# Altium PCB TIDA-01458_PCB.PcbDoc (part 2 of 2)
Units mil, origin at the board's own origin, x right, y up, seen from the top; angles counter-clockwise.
Board outline 4724.41 x 3937.01 mil, 4 copper layers (Top Layer, GND, PWR, Bottom Layer), stack 62.2 mil thick; 188 components, 87 nets, 511 pads, 463 vias.
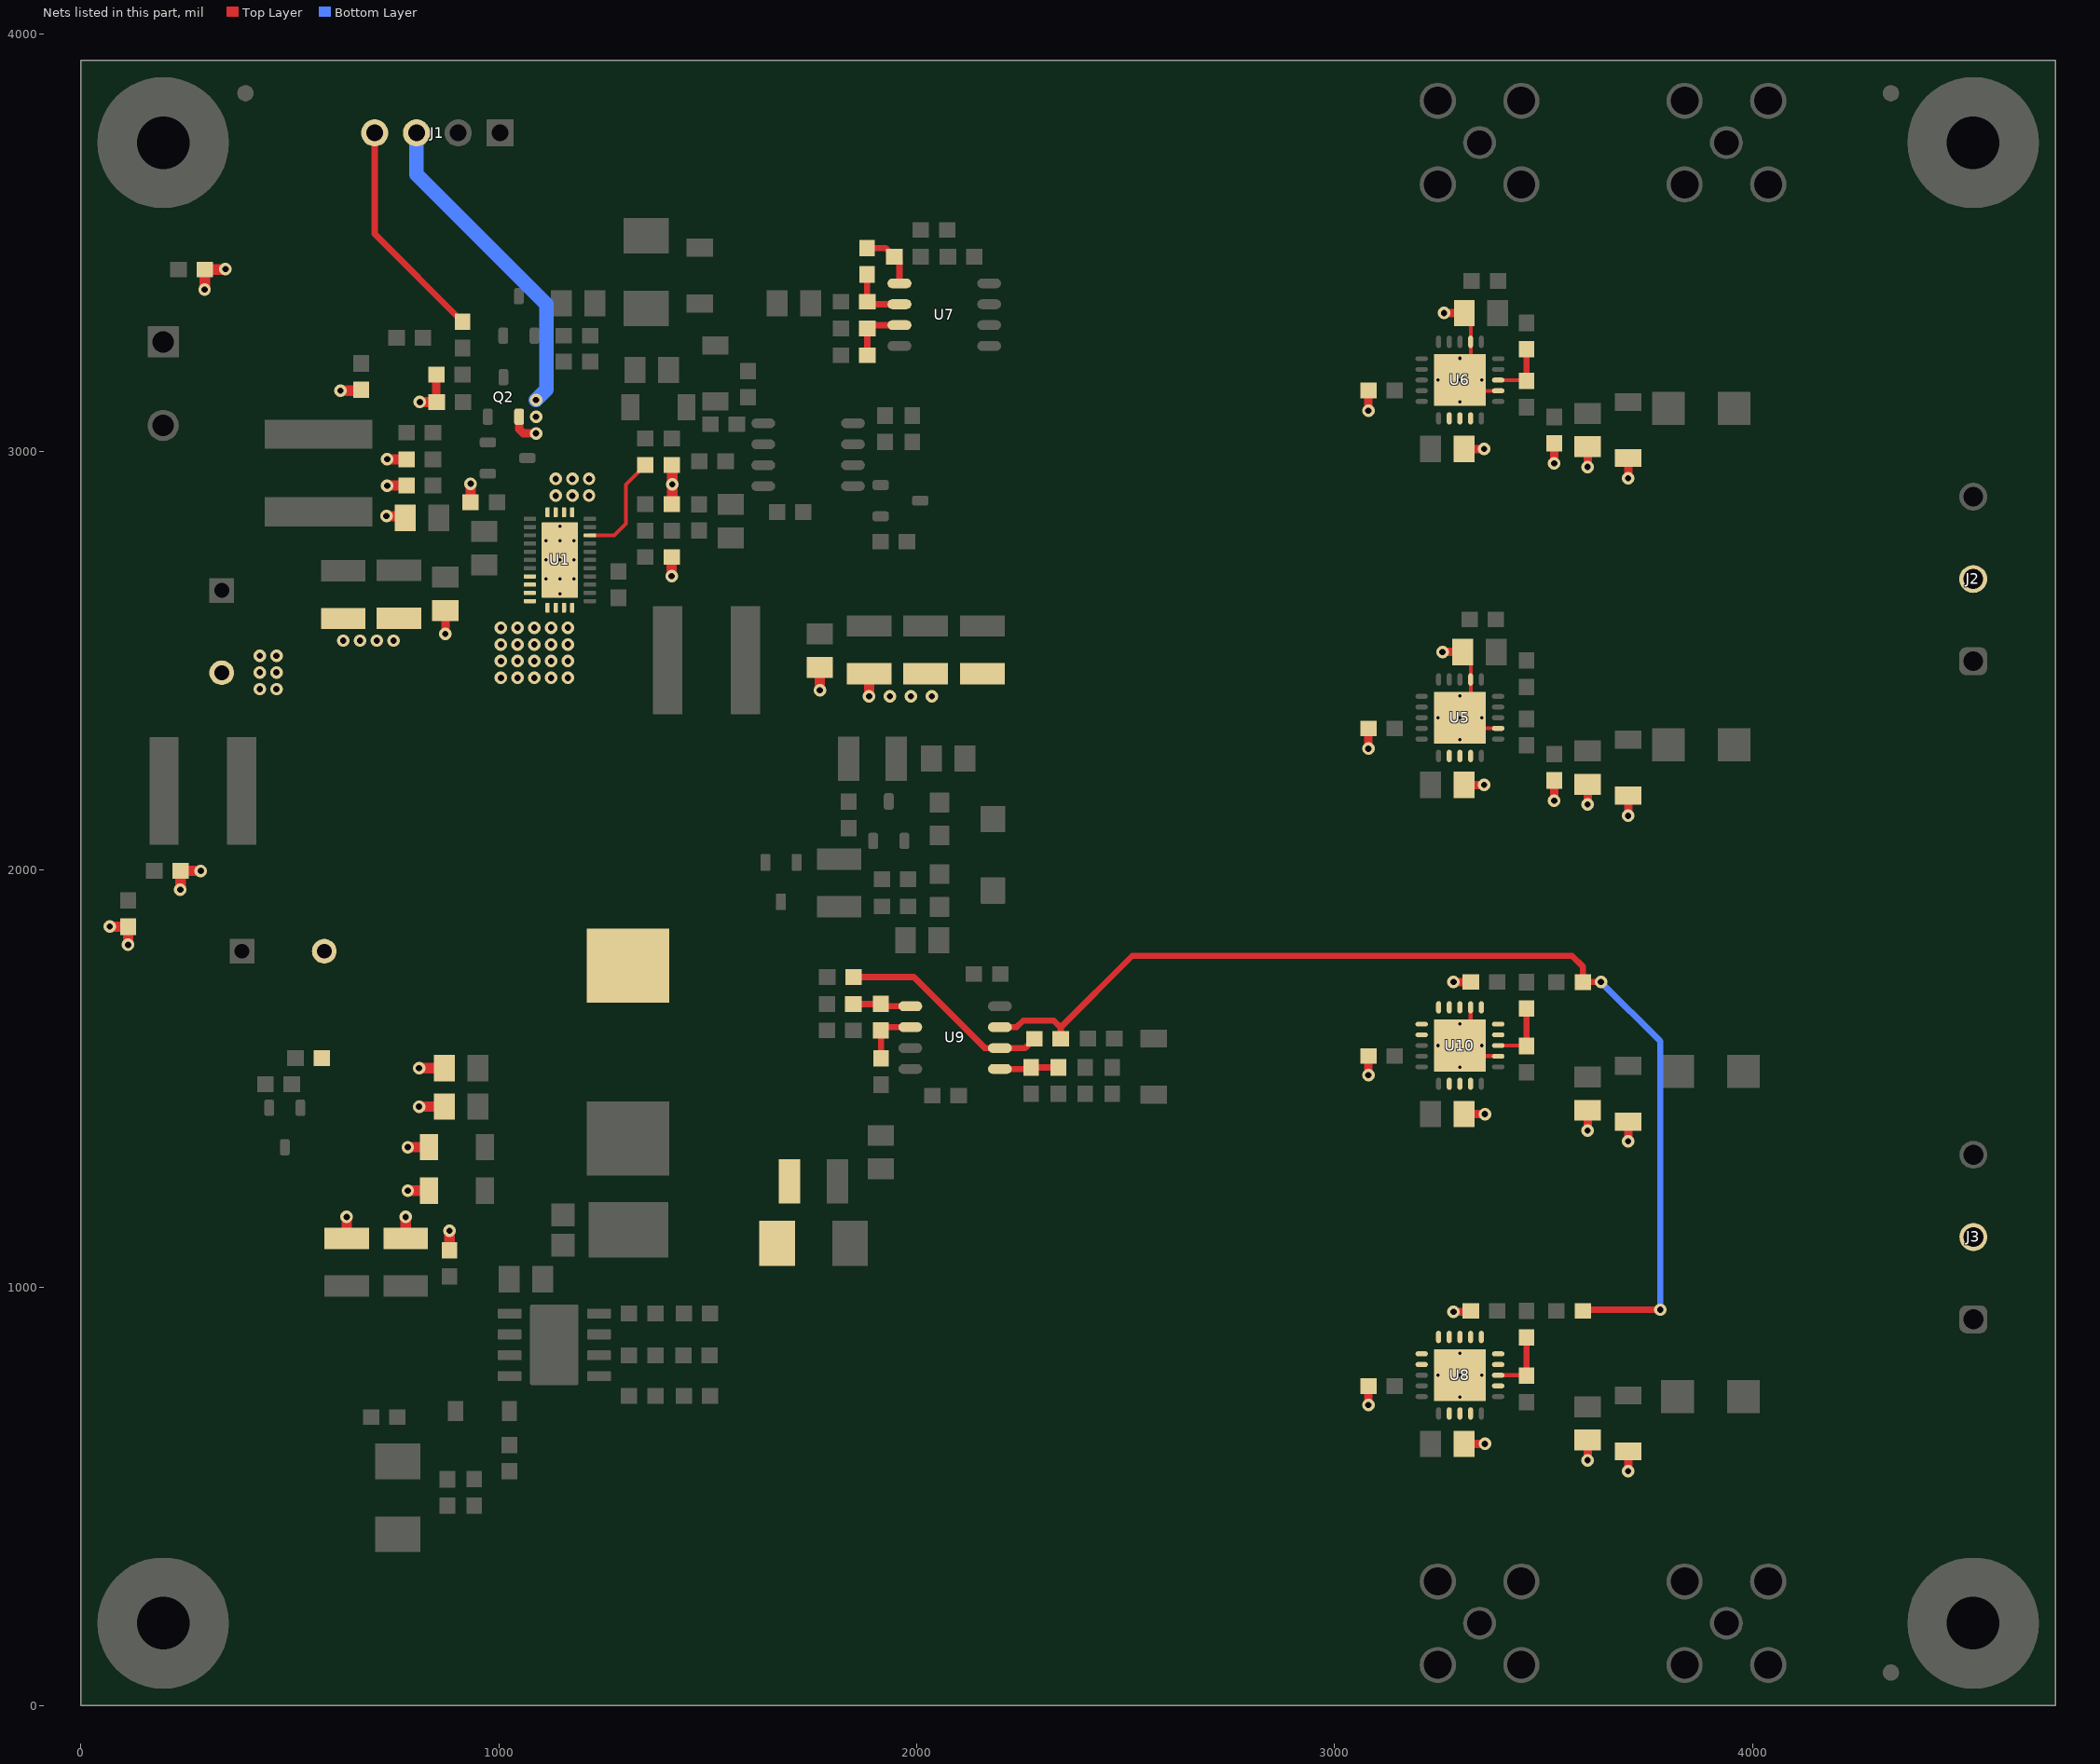
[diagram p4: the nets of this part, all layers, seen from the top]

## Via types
v1: diameter 30, hole 15, Top Layer to Bottom Layer, tented both sides, 424 vias
v2: diameter 19.68, hole 7.87, Top Layer to Bottom Layer, 39 vias

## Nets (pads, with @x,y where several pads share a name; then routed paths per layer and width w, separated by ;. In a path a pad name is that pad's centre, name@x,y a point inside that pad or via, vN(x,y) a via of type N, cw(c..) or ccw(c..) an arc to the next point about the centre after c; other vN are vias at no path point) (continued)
NetR35_2: R35.2 R37.1 U6.3 | length 144.3
  Top Layer w9: U6.3@3391.03,3171.79 3457.21,3171.79 R35.2@3459,3170 R35.2@3459,3189
  Top Layer w15: R35.2@3459,3189 R37.1@3459,3245.54
NetR36_1: R36.1 R39.2 U7.1 | length 142.9
  Top Layer w15: R36.1@1881,3487.75 1925.9,3487.75 R39.2@1946.35,3467.3 1958.57,3455.08 U7.1@1958.57,3403.3
NetR36_2: R36.2 R38.1 U7.2 | length 145.2
  Top Layer w15: R36.2@1881,3424.76 1881,3359.75 R38.1@1881.5,3359.25 1887.45,3353.3 U7.2@1958.57,3353.3
NetR41_1: R41.1 R42.2 U7.3 | length 147
  Top Layer w15: R42.2@1881.5,3229.22 R41.1@1881.5,3295.25 1889.54,3303.3 U7.3@1958.57,3303.3 ; R42.2@1881.54,3231.19 R42.2@1881.97,3230.76
NetR43_1: R43.1 R46.1 U8.3 | length 158
  Top Layer w10: U8.3@3391.03,790.25 R43.1@3457.68,790.25
  Top Layer w15: R43.1@3457.68,790.25 3459,791.57 R46.1@3459,881.01
NetR44_1: R44.1 R45.2 U9.2 | length 141.2
  Top Layer w15: R44.1@1914.72,1548.75 1914.72,1614.76 R45.2@1913.72,1615.76 1921.21,1623.25 U9.2@1984.43,1623.25
NetR45_1: R45.1 R48.1 U9.1 | length 138.7
  Top Layer w15: R48.1@1848.21,1678.25 1848.71,1678.75 R45.1@1913.72,1678.75 1919.21,1673.25 U9.1@1984.43,1673.25
NetR47_2: R47.2 R51.1 R57.2 U9.7 | length 2627.2
  Top Layer w15: U9.7@2199,1623.25 2238.84,1623.25 2254.59,1639 2328,1639 2344.21,1622.79 ; R51.1@2344.21,1595.25 2344.21,1622.79 ; R47.2@3593.5,944 3596.5,947 v1(3779,947) ; v1(3636.82,1731.18) R57.2@3593.5,1731.18 3593.5,1768.5 3568,1794 2515.43,1794 2344.21,1622.79
  Bottom Layer w15: v1(3636.82,1731.18) 3779,1589 v1(3779,947)
NetR50_1: R50.1 R51.2 U9.6 | length 512.1
  Top Layer w15: R50.1@1848.67,1743.23 1992.77,1743.23 2162.75,1573.25 U9.6@2199,1573.25 2259.22,1573.25 R51.2@2281.22,1595.25
NetR52_1: R52.1 R55.1 U10.3 | length 155.6
  Top Layer w9: U10.3@3391.03,1579.25 R52.1@3452.5,1579.25
  Top Layer w15: R52.1@3452.5,1579.25 3454,1577.75 R52.1@3454,1578 ; R55.1@3454,1667.76 3458.93,1662.82 R52.1@3458.93,1578
NetR53_2: R53.2 R54.2 U9.5 | length 141.2
  Top Layer w15: U9.5@2199,1523.25 2270.22,1523.25 R53.2@2273.72,1526.75 R54.2@2338.72,1526.75
NetR58_1: R58.1 U1.9 | length 257
  Top Layer w9: U1.9@1217.85,2800.31 1276.06,2800.31 1304,2828.25 1304,2921.75 R58.1@1350.5,2968.25
PGND_A: C2.2 C3.1 C4.1 C5.1 C6.1 C7.1 C8.2 C9.2 C10.2 C11.1 C12.2 C15.2 C65.2 J1.3 Q2.2 R3.1 R6.1 R10.1 R58.2 R59.1 U1.12 U1.13 U1.14 U1.15 U1.23 U1.24 U1.25 U1.26 U1.27 U1.28 U1.29 U1.30 U1.31 | length 1479.6
  Top Layer w20: C65.2@850.5,3185 850.5,3120.25 R10.1@851.5,3119.25 ; v1(872,2564.25) C6.1@872,2620.25 ; Q2.2@1048.4,3084.01 1048.4,3054.85 1059,3044.25 v1(1089,3044.25) v1@1094,3044.25
  Top Layer w25: v1(621,3146.25) 668.5,3146.25 R59.1@671,3148.76 ; v1(731,2846.25) 757,2846.25 R3.1@761,2842.25 ; v1(733,2919.25) C12.2@768.5,2919.25 ; v1(733,2982.25) C15.2@779.5,2982.25 ; v1(811,3119.25) R10.1@851.5,3119.25 ; R6.1@932.5,2879.25 v1(932.5,2923.76) ; v1(1413.5,2702.76) C3.1@1413.5,2748.25 ; C11.1@1413.5,2875.05 1415,2876.56 v1(1415,2922.25) 1415,2966.88 R58.2@1413.5,2968.39 ; v1(1768,2429.25) C7.1@1768,2484.25 ; v1(1886,2415.25) C9.2@1886,2469.17
  Bottom Layer w15: J1.3@803,3763.25 J1.3@804,3762.25
  Bottom Layer w35: J1.3@803,3763.25 803,3664.25 1114,3353.25 1114,3149.25 v1(1089,3124.25)
  other v1: 1936,2415.25 1986,2415.25 2036,2415.25 428,2432.25 468,2432.25 1005,2459.25 1045,2459.25 1085,2459.25 1125,2459.25 1165,2459.25 428,2472.25 468,2472.25 1005,2499.25 1045,2499.25 1085,2499.25 1125,2499.25 1165,2499.25 428,2512.25 468,2512.25 1005,2539.25 1045,2539.25 1085,2539.25 1125,2539.25 1165,2539.25 628,2548.25 668,2548.25 708,2548.25 748,2548.25 1005,2579.25 1045,2579.25 1085,2579.25 1125,2579.25 1165,2579.25 1136,2895.25 1176,2895.25 1216,2895.25 1136,2935.25 1176,2935.25 1216,2935.25 1089,3084.25
  other v2: 1146,2660.54 1112.54,2695.58 1146,2695.58 1179.46,2695.58 1112.54,2741.25 1146,2741.25 1179.46,2741.25 1112.54,2786.92 1146,2786.92 1179.46,2786.92 1146,2821.96
PGND_B: C23.2 C24.2 C25.2 C26.2 C29.1 C30.1 C31.1 C33.2 C62.1 D4.1 L2.2 R23.1 R60.1 | length 441.7
  Top Layer w25: v1(238,1952.25) 238.5,1952.75 R60.1@238.5,1997.25 v1(287,1997.25) ; C23.2@636,1118.09 v1(636,1169) ; C24.2@777,1118.09 v1(777,1169) ; v1(782.16,1232) C62.1@833.07,1232 ; v1(782.16,1336) C31.1@833.07,1336 ; v1(809.09,1433) C30.1@860,1433 ; v1(809.09,1525) C29.1@860,1525 ; C25.2@882,1093.5 v1(882,1136)
REGM: C49.1 C50.2 C51.1 C53.1 C56.1 C57.2 C58.1 C59.1 C60.1 C61.1 J3.2 R62.1 U8.2 U8.4 U8.5 U8.6 U8.7 U8.8 U8.9 U8.10 U8.11 U8.12 U8.17 U8.18 U8.19 U8.21 U10.2 U10.4 U10.5 U10.6 U10.7 U10.8 U10.9 U10.10 U10.11 U10.12 U10.17 U10.18 U10.19 U10.21 | length 721.4
  Top Layer w10: v2(3299.5,1579.25) 3325.09,1604.84 U10.7@3325.09,1670.79 ; U10.21@3325.09,1553.66 U10.2@3391.03,1553.66
  Top Layer w20: v1(3080.5,719.25) C60.1@3080.5,764.25 C60.1@3080.5,765 ; v1(3080.5,1508.5) C61.1@3080.5,1554.25 ; v1(3284.25,942) C53.1@3325.5,942 ; v1(3284.25,1731.25) C59.1@3325.5,1731.25 ; C51.1@3309,626 v1(3359.25,626) ; C58.1@3309,1415.25 v1(3359.25,1415.25) ; v1(3605,586.75) C49.1@3605,635 ; v1(3605,1376) C56.1@3605,1424.25 ; v1(3702,560.75) C50.2@3702,608.07 ; v1(3702,1350) C57.2@3702,1397.32
  Top Layer w25: v1(69,1864.25) 69.5,1863.76 R62.1@113,1863.76 v1(113,1820.25)
  other v2: 3299.5,738.09 3247.33,790.25 3299.5,790.25 3351.66,790.25 3299.5,842.42 3299.5,1527.09 3247.33,1579.25 3351.66,1579.25 3299.5,1631.42
REGP: C34.1 C35.2 C36.2 C37.1 C38.1 C39.1 C40.1 C41.2 C42.2 C43.1 C46.1 C47.1 J2.2 R61.1 U5.2 U5.7 U5.17 U5.18 U5.19 U5.21 U6.2 U6.7 U6.17 U6.18 U6.19 U6.21 | length 1232.8
  Top Layer w9: C39.1@3310,2521 3325.09,2505.91 U5.7@3325.09,2455.32 3325.09,2389.38 v2(3299.5,2363.79) 3325.09,2338.2 U5.2@3391.03,2338.2 ; C47.1@3310,3332.25 3325.09,3317.17 U6.7@3325.09,3263.32 3325.09,3197.38 v2(3299.5,3171.79) 3325.09,3146.2 U6.2@3391.03,3146.2
  Top Layer w20: v1(3080.5,2289.75) C38.1@3080.5,2338 ; v1(3080.5,3098.75) C46.1@3080.5,3147 ; v1(3257.75,2521) C39.1@3306,2521 ; v1(3261.75,3332.25) C47.1@3310,3332.25 ; C37.1@3309,2203 v1(3357.25,2203) ; C43.1@3309,3007 v1(3357.25,3007) ; v1(3525,2165.5) C36.2@3525,2213.76 ; v1(3525,2972.25) C42.2@3525,3020.5 ; v1(3605,2156) C34.1@3605,2204.25 ; v1(3605,2964) C40.1@3605,3012.25 ; v1(3702,2129.07) C35.2@3702,2177.32 ; v1(3702,2937.07) C41.2@3702,2985.32
  Top Layer w25: v1(296,3388.25) 296.5,3388.75 R61.1@296.5,3436.25 345,3436.25 v1(346,3437.25)
  other v2: 3299.5,2311.62 3247.33,2363.79 3351.66,2363.79 3299.5,2415.95 3299.5,3119.62 3247.33,3171.79 3351.66,3171.79 3299.5,3223.95
SYNC: J1.4 R30.1 | length 538.7
  Top Layer w15: J1.4@703,3763.25 703,3521.5 R30.1@913,3311.5
pads on no net: FID1.1 FID2.1 FID3.1 H1.1 H2.1 H5.1 H6.1 U1.16 U1.31A U4.9@1132.72,863 U5.4 U5.5 U5.6 U5.8 U5.9 U5.10 U5.11 U5.12 U6.4 U6.5 U6.6 U6.8 U6.9 U6.10 U6.11 U6.12

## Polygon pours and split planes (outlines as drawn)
PGND_B on Top Layer "GND-No Net" (solid, pour order 236): 551,1831 551,1103 585,1069 901,1069 906,1074 906,1613 956,1663 1436,1663 1585,1514 1585,1049 1609,1025 1694,1025 1726,1057 1726,1748 1598,1876 822,1876 596,1876
-VO on Top Layer "GND-No Net" (solid, pour order 230): 920,1514 920,1220 1045,1095 1071,1069 1071,1015 1071,470 1015,414 948,347 784,347 457,347 415,305 398,288 398,104 398,67 462,3 526,3 2886,3 3000,117 3000,1314 2943,1371 2599,1371 2168,1371 2123,1326 2083,1286 2083,1056 2041,1014 1739,1014 1667,1014 1617,964 1602,949 1602,761 1602,716 1563,677 1241,677 1221,697 1194,724 1194,843 1194,860 1210,876 1216,876 1533,876 1536,879 1536,896 1532,900 1210,900 1203,907 1191,919 1191,1607 1157,1641 959,1641 920,1602
PGND_A on Top Layer "Top Layer-No Net" (solid, remove dead copper, pour order 146): 715,2824.25 722,2817.25 732,2807.25 757,2807.25 799,2807.25 803,2811.25 803,2864.25 803,2998.25 798,3003.25 797,3004.25 738,3004.25 732,3004.25 715,2987.25
+3.3V on Top Layer "Bottom Layer-No Net" (solid, remove dead copper, pour order 109): 1195,3363.25 1195,3197.25 1202.2,3190.05 1256,3190.05 1282.98,3217.02 1282.98,3234 1295.99,3247.01 1445.01,3247.01 1513,3315 1513,3385.25 1484,3414.25 1439,3414.25 1217,3414.25 1195,3392.25
NetC2_1 on Top Layer "Bottom Layer-No Net" (solid, remove dead copper, pour order 145): 564,2903.25 691,2903.25 697,2897.25 699,2895.25 699,2820.25 692,2813.25 689,2810.25 663,2810.25 424,2810.25 368,2754.25 368,2716.25 381,2703.25 413,2703.25 497,2787.25 642,2787.25 869,2787.25 888,2768.25 892,2764.25 1052,2764.25 1082,2764.25 1086,2760.25 1087,2759.25 1087,2733.25 1087,2718.25 1084,2715.25 1017,2715.25 1005,2703.25 976,2674.25 842,2674.25 469,2674.25 422,2627.25 308,2627.25 303,2632.25 294,2641.25 294,2767.25 331,2804.25 331,2889.25 345,2903.25
24VIN on Top Layer "Bottom Layer-No Net" (solid, remove dead copper, pour order 144): 1763,2275.25 1763,2173.25 1781,2155.25 1796,2140.25 1834,2140.25 1938,2140.25 1944,2146.25 1945,2147.25 1945,2175.25 1945,2181.25 1941,2185.25 1916,2185.25 1893,2208.25 1878,2223.25 1878,2262.25 1878,2308.25 1866,2320.25 1830,2320.25 1800,2320.25 1763,2283.25
24VIN on Top Layer "Bottom Layer-No Net" (solid, remove dead copper, pour order 140): 117,3111.25 675,3111.25 699,3087.25 699,2988.25 670,2959.25 330,2959.25 310,2939.25 310,2816.25 245,2751.25 245,2062.25 227,2044.25 61,2044.25 26,2079.25 26,2206.25 26,3050.15 52,3076.15 87.1,3111.25
16V on Top Layer "Bottom Layer-No Net" (solid, remove dead copper, pour order 107): 1951,2079.25 1951,1965.25 1958,1958.25 1960,1956.25 1991,1956.25 2105,1956.25 2121,1972.25 2121,2094.25 2105,2110.25 1975,2110.25 1962,2110.25 1951,2099.25
+VO on Top Layer "Bottom Layer-No Net" (solid, remove dead copper, pour order 106): 1520,2369.25 1536,2353.25 1669,2353.25 1675,2359.25 1675,2496.25 1712,2533.25 1958,2533.25 2204,2533.25 2218.72,2547.98 2218.72,2638.53 2192,2665.25 1694,2665.25 1669,2690.25 1626,2733.25 1626,2750.25 1626,2802.25 1592,2836.25 1540,2836.25 1465,2836.25 1457.5,2828.75 1457.5,2727.75 1520,2665.25
NetC1_1 on Top Layer "Bottom Layer-No Net" (solid, remove dead copper, pour order 99): 1209,2726.25 1234,2726.25 1247,2726.25 1254,2719.25 1254,2681.25 1264,2671.25 1352,2671.25 1446,2671.25 1464,2671.25 1493,2642.25 1493,2369.25 1476,2352.25 1327,2352.25 1203,2476.25 1203,2720.25
PGND_A on Top Layer "Bottom Layer-No Net" (solid, remove dead copper, pour order 98): 860,2645.25 466,2645.25 305,2484.25 305,2409.25 334.19,2380.06 751.19,2380.06 919,2212.25 1321,2212.25 1675,2212.25 1815,2352.25 2197,2352.25 2224.81,2380.06 2224.81,2491.06 2203,2512.88 2166,2512.88 1739.38,2512.88 1701,2474.5 1701,2354.25 1675,2328.25 1321,2328.25 1188,2461.25 1188,2544.25 1188,2648.25 1188,2845.25 1257,2914.25 1257,3071 1182.25,3145.75 1085.5,3145.75 1072,3132.25 1072,3034.25 1104,3002.25 1104,2870.25 1104,2831.25 1104,2716.25 1097,2709.25 1092,2704.25 1053,2704.25 1038,2689.25 994,2645.25 905,2645.25
NetC49_2 on Top Layer "GND-No Net" (solid, pour order 148): 3394,748 3508,748 3532,772 3547,787 3735,787 3859,787 3868,778 3870,776 3870,712 3870,679 3615,679 3353,679 3348,679 3341,686 3341,713 3345,717 3355,717 3366,717 3369,720 3374,725 3374,735 3374,744 3378,748
NetC56_2 on Top Layer "GND-No Net" (solid, pour order 150): 3394,1537 3508,1537 3532,1561 3547,1576 3735,1576 3859,1576 3868,1567 3870,1565 3870,1501 3870,1487 3851,1468 3615,1468 3353,1468 3348,1468 3341,1475 3341,1502 3345,1506 3355,1506 3366,1506 3369,1509 3374,1514 3374,1524 3374,1533 3378,1537
NetC34_2 on Top Layer "GND-No Net" (solid, pour order 152): 3394,2321.54 3508,2321.54 3532,2345.54 3547,2360.54 3735,2360.54 3859,2360.54 3868,2351.54 3870,2349.54 3870,2285.54 3870,2271.54 3851,2252.54 3615,2252.54 3353,2252.54 3348,2252.54 3341,2259.54 3341,2286.54 3345,2290.54 3355,2290.54 3366,2290.54 3369,2293.54 3374,2298.54 3374,2308.54 3374,2317.54 3378,2321.54
NetC40_2 on Top Layer "GND-No Net" (solid, pour order 154): 3394,3129.54 3508,3129.54 3532,3153.54 3547,3168.54 3735,3168.54 3870,3168.54 3870,3093.54 3870,3079.54 3851,3060.54 3615,3060.54 3353,3060.54 3348,3060.54 3341,3067.54 3341,3094.54 3345,3098.54 3355,3098.54 3366,3098.54 3369,3101.54 3374,3106.54 3374,3116.54 3374,3125.54 3378,3129.54
REGP on Top Layer "Top Layer-No Net" (solid, remove dead copper, pour order 158): 3100.99,2336.25 3100.99,2184.25 3135.99,2149.25 3256.49,2149.25 3271.5,2164.25 3271.5,2290.25 3237.64,2324.11 3237.64,2340.39 3237.64,2417.52 3241.7,2421.58 3246.37,2426.25 3290.99,2426.25 3309.8,2426.25 3317.41,2433.86 3317.99,2434.45 3317.99,2460.25 3317.99,2475.25 3313.99,2479.25 3308.99,2484.25 3291.99,2484.25 3251.79,2484.25 3231.5,2504.55 3231.5,2542.25 3247.5,2558.25 3306.99,2558.25 3329.99,2558.25 3330.99,2559.25 3331.99,2558.25 3331.99,2436.25 3342.99,2425.25 3361.35,2406.89 3361.35,2340.39 3361.35,2310.06 3357.29,2305.99 3344.2,2305.99 3331.99,2293.79 3331.99,2247.62 3337.18,2242.44 3342.36,2237.25 3374.99,2237.25 3806.75,2237.25 4058,1986 4058,1874 4018,1834 2956,1834 2834,1956 2834,2314 2882.85,2362.85 3092.35,2362.86 3094.85,2362.86 3100.99,2356.71
+VO on Top Layer "Bottom Layer-No Net" (solid, remove dead copper, pour order 162): 3255.5,2979.26 3249.5,2973.25 3144.04,2973.25 3118.07,2999.23 3118.07,3012.57 3118.07,3058.82 3186.5,3127.25 3220.5,3127.25 3226.5,3121.25 3226.5,3109.25 3226.5,3105.25 3231.5,3100.25 3234.5,3097.25 3248.5,3097.25 3250.5,3097.25 3255.5,3092.25
+VO on Top Layer "Bottom Layer-No Net" (solid, remove dead copper, pour order 164): 3255.5,2171.26 3249.5,2165.25 3144.04,2165.25 3118.07,2191.23 3118.07,2204.57 3118.07,2250.82 3186.5,2319.25 3220.5,2319.25 3226.5,2313.25 3226.5,2301.25 3226.5,2297.25 3231.5,2292.25 3234.5,2289.25 3248.5,2289.25 3250.5,2289.25 3255.5,2284.25
-VO on Top Layer "Bottom Layer-No Net" (solid, remove dead copper, pour order 166): 3255.5,1386.72 3249.5,1380.72 3144.04,1380.72 3118.07,1406.69 3118.07,1420.03 3118.07,1466.29 3186.5,1534.72 3220.5,1534.72 3226.5,1528.72 3226.5,1516.72 3226.5,1512.72 3231.5,1507.72 3234.5,1504.72 3248.5,1504.72 3250.5,1504.72 3255.5,1499.72
-VO on Top Layer "Bottom Layer-No Net" (solid, remove dead copper, pour order 168): 3255.5,597.72 3249.5,591.72 3144.04,591.72 3118.07,617.69 3118.07,631.03 3118.07,677.29 3186.5,745.72 3220.5,745.72 3226.5,739.72 3226.5,727.72 3226.5,723.72 3231.5,718.72 3234.5,715.72 3248.5,715.72 3250.5,715.72 3255.5,710.72
REGM on Top Layer "Top Layer-No Net" (solid, remove dead copper, pour order 176): 3103,1573 3103,1390.87 3136.88,1356.99 3249.88,1356.99 3272.38,1379.48 3272.38,1503.52 3272.38,1520.49 3264.88,1527.99 3243.58,1549.29 3243.58,1583.29 3226.88,1599.99 3198.88,1599.99 3194.88,1603.99 3194.88,1719.13 3229.72,1753.98 3307.88,1753.98 3315.88,1753.99 3345.88,1753.99 3347.88,1751.99 3348.88,1750.99 3348.88,1744.99 3348.88,1706.99 3368.88,1686.99 3406.88,1648.99 3406.88,1613.99 3406.88,1606.11 3406.88,1602.99 3404.88,1600.99 3369.88,1600.99 3362.88,1593.99 3362.88,1571.65 3371.45,1563.08 3374.28,1560.25 3404,1560.25 3406.88,1557.37 3406.88,1550.99 3405.88,1549.99 3404.88,1548.99 3399.88,1548.99 3368.73,1548.99 3357.63,1537.88 3346.67,1537.88 3327,1518.21 3327,1467.25 3343.26,1450.99 3775.02,1450.99 3920.99,1305.01 3921,1162 3861,1102 3092,1102 3025,1169 3025,1545.02 3056.23,1576.25 3099.75,1576.25
NetD2_3 on Top Layer "GND-No Net" (solid, pour order 188): 1206,928 1217,917 1330,917 1335,922 1335,933 1335,962.78 1419,1046.78 1419,1441 1395,1465 1220,1465 1206,1451
NetC23_1 on Top Layer "GND-No Net" (solid, pour order 194): 463,1109 519,1053 1044,1053 1056,1041 1056,883 1056,874 1055,873 1052,870 902,870 802,770 454,770 298,926 298,2288 332,2322 334,2324 381,2324 422,2324 463,2283
NetD8_2 on Top Layer "GND-No Net" (solid, pour order 198): 3915,1551 3915,1344 3948,1311 3994,1265 4500,1265 4550,1265 4565,1280 4585,1300 4585,1339 4585,1482 4517,1550 4495,1572 4009,1572 3935,1572 3915,1552
NetD7_2 on Top Layer "GND-No Net" (solid, pour order 200): 4460,977 4554,977 4578,953 4578,796 4512,730 4462.75,680.75 3994,680.75 3947.25,680.75 3929,699 3929,863 4003,937 4043,977 4441,977
NetD6_1 on Top Layer "GND-No Net" (solid, pour order 202): 3903,2930.41 3947.56,2885.85 3993.56,2839.85 4499.56,2839.85 4549.56,2839.85 4564.56,2854.85 4584.56,2874.85 4584.56,2913.85 4584.56,3056.85 4516.56,3124.85 4476.41,3165 3923,3165 3903,3145
NetD5_1 on Top Layer "GND-No Net" (solid, pour order 204): 4459.56,2551.85 4553.56,2551.85 4577.56,2527.85 4577.56,2370.85 4511.56,2304.85 4462.31,2255.6 3993.56,2255.6 3917.4,2255.6 3910,2263 3910,2419.29 4002.56,2511.85 4042.56,2551.85 4440.56,2551.85
-3.3V on Top Layer "GND-No Net" (solid, pour order 228): 2008.73,1447 2008.73,1350.73 1979,1321 1974,1316 1921,1316 1790,1316 1779,1305 1775,1301 1775,1085 1775,1060 1788,1047 1794,1041 1893,1041 1992,1041 2040,1089 2060,1109 2060,1441 2060,1475 2056,1479 2039,1479 2013.73,1479 2008.73,1474
REGM on Top Layer "Top Layer-No Net" (solid, remove dead copper, pour order 240): 3103,784 3103,601.87 3136.88,567.99 3249.88,567.99 3272.38,590.48 3272.38,714.52 3272.38,731.49 3264.88,738.99 3243.58,760.29 3243.58,794.29 3226.88,810.99 3198.88,810.99 3194.88,814.99 3194.88,930.13 3229.72,964.98 3307.88,964.98 3315.88,964.99 3345.88,964.99 3347.88,962.99 3348.88,961.99 3348.88,955.99 3348.88,917.99 3368.88,897.99 3406.88,859.99 3406.88,824.99 3406.88,817.11 3406.88,813.99 3404.88,811.99 3369.88,811.99 3362.88,804.99 3362.88,782.65 3371.45,774.08 3374.28,771.25 3404,771.25 3406.88,768.37 3406.88,761.99 3405.88,760.99 3404.88,759.99 3399.88,759.99 3368.73,759.99 3357.63,748.88 3346.67,748.88 3327,729.21 3327,678.25 3343.26,661.99 3817.01,661.99 3911,568 3911,399.87 3871.5,360.37 3576.64,360.37 3050.63,360.37 3025,386 3025,756.02 3056.23,787.25 3099.75,787.25
REGP on Top Layer "Top Layer-No Net" (solid, remove dead copper, pour order 242): 3100.99,3144.25 3100.99,2992.25 3135.99,2957.25 3256.49,2957.25 3271.5,2972.25 3271.5,3098.25 3237.64,3132.11 3237.64,3148.39 3237.64,3225.52 3241.7,3229.58 3246.37,3234.25 3290.99,3234.25 3309.8,3234.25 3317.41,3241.86 3317.99,3242.45 3317.99,3268.25 3317.99,3283.25 3313.99,3287.25 3308.99,3292.25 3291.99,3292.25 3251.79,3292.25 3231.5,3312.55 3231.5,3350.25 3247.5,3366.25 3306.99,3366.25 3329.99,3366.25 3330.99,3367.25 3331.99,3366.25 3331.99,3244.25 3342.99,3233.25 3361.35,3214.89 3361.35,3148.39 3361.35,3118.06 3357.29,3113.99 3344.2,3113.99 3331.99,3101.79 3331.99,3055.62 3337.18,3050.44 3342.36,3045.25 3374.99,3045.25 3760.75,3045.25 4062,2744 4062,2671 4039,2648 2944,2648 2831,2761 2831,3148 2853.85,3170.85 3092.35,3170.86 3097.14,3170.86 3100.99,3167.01
PGND_A on GND "Bottom Layer-No Net" (solid, remove dead copper, pour order 111): 859,3168.25 1071,3168.25 1104,3135.25 1104,3037.25 970,2903.25 970,2888.25 970,2756.25 1000,2726.25 1049,2726.25 1074,2751.25 1074,2895.25 1147.99,2969.24 1460.01,2969.24 1656,2773.25 2020,2773.25 2210.15,2583.1 2210.15,2466.25 2210.15,2398.4 2195,2383.25 2187,2375.25 2143,2375.25 1687,2375.25 379,2375.25 221,2533.25 221,2969.25 420,3168.25
AGND1 on GND "Bottom Layer-No Net" (solid, remove dead copper, pour order 134): 802,3200.25 814,3188.25 1074,3188.25 1121,3141.25 1121,3029.25 991,2899.25 991,2760.25 1009,2742.25 1039,2742.25 1056,2759.25 1056,2899.25 1149,2992.25 1477,2992.25 1660,2809.25 1960,2809.25 1999,2848.25 1999,3229.29 1901.04,3327.25 1048,3327.25 816,3327.25 802,3313.25
AGND on GND "Bottom Layer-No Net" (solid, remove dead copper, pour order 135): 25,2362.25 25,1923.25 44,1904.25 165.25,1904.25 193,1932 193,3210.25 766,3210.25 779,3223.25 779,3299.25 771,3307.25 258,3307.25 250,3315.25 250,3445.25 236,3459.25 174,3459.25 159,3444.25 159,3323.25 143,3307.25 52,3307.25 27,3282.25 25,3280.25 25,2361.25
REGP on GND "GND-No Net" (solid, pour order 180): 4730.66,2140.66 4649,2059 4586,1996 3527,1996 3067,1996 2985,2078 2829,2234 2829,2435 2829,3133 2581,3381 2340,3622 2074,3622 1253,3622 1112,3481 994,3363 299,3363 291,3363 280,3374 276,3378 276,3406 276,3436 276,3489 291,3504 367,3504 925,3504 1100,3679 1198,3777 1847,3777 2619,3777 2621,3779 2880,3520 4043,3520 4653,3520 4734.45,3438.55
REGM on GND "GND-No Net" (solid, pour order 184): 3181,1805 4605,1805 4705,1705 4705,783 4647,725 4414,492 3871,492 3292,492 2831,31 1688,31 638,31 189,480 14,655 14,1847 48,1881 128,1881 189,1820 189,783 574,398 769,203 2520,203 3058,741 3058,1682
-VO on GND "GND-No Net" (solid, pour order 208): 924,1537 924,1214 924,399 1080,243 2500,243 3000,743 3000,1724.41 2787.41,1937 1053,1937 924,1808
PGND_B on GND "GND-No Net" (solid, pour order 216): 908,1543 908,986 890,968 860,938 578,938 307,938 212,1033 215,1036 215,1936 215,1988 240,2013 252,2025 404,2025 821,2025 910,1936
24VIN on PWR "Bottom Layer-No Net" (solid, remove dead copper, pour order 143): 244,2500.25 348.25,2396 1675,2396 1802.8,2268.2 1802.8,2130.05 1747,2074.25 612,2074.25 154,2074.25 93,2074.25 37,2130.25 24,2143.25 24,2749.25 24,3048.25 88,3112.25 497,3112.25 526,3083.25 526,2799.25 509,2782.25 277,2782.25 244,2749.25
NetC2_1 on PWR "Bottom Layer-No Net" (solid, remove dead copper, pour order 117): 305,2631.25 338,2598.25 979,2598.25 1073,2692.25 1073,2925.25 1202.5,3054.75 1202.5,3390.25 1158.25,3434.5 914,3434.5 722,3434.5 588.88,3301.38 588.88,2797.13 539,2747.25 336,2747.25 305,2716.25
-VO on PWR "GND-No Net" (solid, pour order 210): 100,1648 36,1584 -16,1532 -16,166 142,8 4593,8 4744,159 4744,1525 4569,1700 152,1700
16V on PWR "GND-No Net" (solid, pour order 212): 2091,3543 2152,3543 2158,3537 2158,3493 2152,3487 2141,3476 2115,3476 1733,3476 1692,3435 1692,2816 1692,2650 1819,2523 2225,2117 2225,2048 2225,1877 2225,1791 2214,1780 2209,1775 2182,1775 2104,1775 2083,1796 2083,1940 2083,1987 2083,2019 1567.46,2534.54 1567.46,3488.46 1622,3543
+VO on PWR "GND-No Net" (solid, pour order 214): 1717.94,2649.52 1775.94,2591.52 2332.94,2591.52 2571.94,2352.52 2897.46,2027 3721,2027 3778,2084 3778,3311 3634.48,3454.52 1870.94,3454.52 1746.94,3454.52 1717.94,3425.52
PGND_A on Bottom Layer "Bottom Layer-No Net" (solid, remove dead copper, pour order 137): 548,3074.25 548,2647.25 467,2566.25 337,2566.25 297,2526.25 297,2385.25 360,2322.25 692,2322.25 2012,2322.25 2051,2361.25 2051,2541.25 2008,2584.25 1701,2584.25 1617,2668.25 1617,3078.25 1533.87,3161.38 608.13,3161.38 548,3101.25
+3.3V on Bottom Layer "Top Layer-No Net" (solid, remove dead copper, pour order 101): 1227,3297.25 1227,3207.25 1238,3196.25 1240,3194.25 1285,3194.25 1395.25,3194.25 1500,3299 1500,3349 1485.75,3363.25 1268,3363.25 1227,3322.25
REGM on Bottom Layer "GND-No Net" (solid, pour order 220): 4382,1704 4382,626 4284,528 3124,528 3087,565 3028,624 3028,1730 3069,1771 3154,1856 4230,1856
REGP on Bottom Layer "GND-No Net" (solid, pour order 222): 3022,3133 3022,2160 3095,2087 3668,2087 4349,2087 4395,2133 4395,3281 4199,3477 3222,3477 3022,3277
AGND on Bottom Layer "GND-No Net" (solid, pour order 250): -0.38,117.38 117,0 4605,0 4724.41,119.41 4724.41,3808.59 4595.99,3937.01 105.01,3937.01 -12.33,3819.67

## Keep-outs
Keep-Out Layer:
  the board outline again, w10
  text ".Layer_Name" at 28,-799.24 h60

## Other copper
Top Layer:
  text ".Layer_Name" at 28,-799.24 h60
GND:
  text ".layer_Name" at 34,-801.75 h60
PWR:
  text ".layer_Name" at 25,-801.75 h60
Bottom Layer:
  text ".Layer_Name" at 28,-799.24 h60

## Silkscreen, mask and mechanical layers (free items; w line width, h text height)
Top Overlay:
  lines w6: 738,3104.25 738,2953.25 740,2951.25 ; 800,3199.25 804,3195.25 804,3083.25 ; 1401,878 1411,888 1540,888 ; 1609,3091 1632,3091 1650,3109 1650,3158 1660,3168 ; 1882,1813 1887,1818 1887,1874
  text "*" at 1729,3107 h30
  text "*" at 1575,2915 h30
  text "TIDA-01458-E1" at 512,75 h70
  text ".Layer_Name" at 28,-799.24 h60
Bottom Overlay:
  text ".Layer_Name" at 28,-799.24 h60
Top Paste:
  text ".Layer_Name" at 28,-799.24 h60
Bottom Paste:
  text ".Layer_Name" at 28,-799.24 h60
Top Solder:
  text ".Layer_Name" at 28,-799.24 h60
  text ".Layer_Name" at 28,-799.24 h60
Bottom Solder:
  text ".Layer_Name" at 28,-799.24 h60
Drill Guide:
  text ".Layer_Name" at 28,-799.24 h60
M1 Board Outline:
  the board outline again, w10
M2 Board Dimensions:
  rectangle: -424,-340.75 -49,-215.75
  rectangle: -549,-215.75 -424,-90.75
  lines w7: -549,-215.75 451,-215.75 ; -424,-340.75 -424,-90.75 ; -299,-340.75 -299,-90.75 ; -49,-340.75 -49,-90.75 ; 201,-340.75 201,-90.75 ; -549,-340.75 -549,-90.75 451,-90.75 451,-340.75 -549,-340.75
M3 3D STEP Top:
  text ".Layer_Name" at 28,-799.24 h60
M4 3D STEP Bottom:
  text ".Layer_Name" at 28,-799.24 h60
M5 Assembly Top:
  lines w10: -841,-870.91 5759,-870.91 ; -841,-667.58 5761,-667.58 ; -841,-464.25 -841,-1074.25 3164,-1074.25 5761,-1074.25 5761,-464.25 -840.5,-464.25 -840.5,-1074.25 735,-1074.25 ; 1624,-1074.25 1624,-464.25 ; 2891,-667.58 2891,-464.25 ; 3731,-667.58 3731,-464.25 ; 4353,-1080.75 4353,-877.91
  text "COMPONENTS MARKED 'DNP' SHOULD NOT BE POPULATED." at 604.5,-259.25 h60
  text "ASSEMBLY VARIANT:" at 604,-374.75 h60
  text ".VariantName" at 1640,-374.75 h60
  text "PCB VIEWED FROM TOP SIDE" at -777.5,-596.41 h60
  text "BOARD #:" at 1699,-596.41 h60
  text ".PRJ_Number" at 2244.5,-596.41 h60
  text "REV:" at 3089,-596.41 h60
  text ".PCB_Rev" at 3380.5,-596.41 h60
  text "SVN REV:" at 3927,-596.41 h60
  text ".VersionControl_RevNumber" at 4433,-596.41 h60
  text "LAYER NAME =" at -777.5,-799.24 h60
  text "TID #:" at 1699,-799.75 h60
  text ".TID" at 2244.5,-799.75 h60
  text ".layer_Name" at 19,-801.75 h60
  text "PLOT NAME =" at -777.5,-1005.08 h60
  text ".plot_File_Name" at 28,-1005.08 h60
  text "GENERATED    :" at 1701,-1005.08 h60
  text ".Print_Date" at 2570.5,-1005.08 h60
  text ".Print_Time" at 3299.5,-1005.08 h60
  text "TEXAS INSTRUMENTS" at 4564,-1005.08 h60
M6 Assembly Bottom:
  lines w10: -841.5,-668.08 5760.5,-668.08 ; -839.5,-871.41 5760.5,-871.41 ; 566.5,-1081.25 566.5,-878.41 ; 1188.5,-668.08 1188.5,-464.75 ; 2028.5,-668.08 2028.5,-464.75 ; 3295.5,-1074.75 3295.5,-464.75 ; 4184.5,-1074.75 5760,-1074.75 5760,-464.75 -841.5,-464.75 -841.5,-1074.75 1755.5,-1074.75 5760.5,-1074.75 5760.5,-464.75
  text "COMPONENTS MARKED 'DNP' SHOULD NOT BE POPULATED." at 5553,-258.75 h60
  text ".VariantName" at 4509,-374.75 h60
  text "ASSEMBLY VARIANT:" at 5548,-374.75 h60
  text ".VersionControl_RevNumber" at 486.5,-596.91 h60
  text "SVN REV:" at 992.5,-596.91 h60
  text ".PCB_Rev" at 1539,-596.91 h60
  text "REV:" at 1830.5,-596.91 h60
  text ".PRJ_Number" at 2675,-596.91 h60
  text "BOARD #:" at 3220.5,-596.91 h60
  text "PCB VIEWED FROM BOTTOM SIDE" at 5697,-596.91 h60
  text "LAYER NAME =" at 5692,-798.75 h60
  text ".TID" at 2675,-800.25 h60
  text "TID #:" at 3220.5,-800.25 h60
  text ".layer_Name" at 4875,-801.75 h60
  text "TEXAS INSTRUMENTS" at 355.5,-1005.58 h60
  text ".Print_Time" at 1620,-1005.58 h60
  text ".Print_Date" at 2349,-1005.58 h60
  text "GENERATED    :" at 3218.5,-1005.58 h60
  text ".plot_File_Name" at 4891.5,-1005.58 h60
  text "PLOT NAME =" at 5697,-1005.58 h60
M9 Title Sheet:
  drawing of 57 lines, arcs and shapes, not listed
  text "1" at 190.84,8095.75 h70
  text "2" at 2686.5,8095.75 h70
  text "3" at 5175.84,8095.75 h70
  text "4" at 7682.51,8095.75 h70
  text "5" at 10181.5,8095.75 h70
  text "6" at 12686.5,8095.75 h70
  text "A" at -965.5,6952.75 h70
  text "A" at 13834.5,6952.75 h70
  text "B" at -965.5,4572.75 h70
  text "B" at 13834.5,4572.75 h70
  text "C" at -965.5,2197.75 h70
  text "C" at 13834.5,2197.75 h70
  text "PROJECT TITLE:" at 10794.5,336.75 h45
  text ".PRJ_Title" at 10844.5,203.42 h60
  text "DESIGNED FOR:" at 10794.5,35.75 h45
  text ".PRJ_Customer" at 10844.5,-104.25 h70
  text "D" at -965.5,-172.25 h70
  text "D" at 13834.5,-172.25 h70
  text "FILE NAME:" at 10794.5,-264.25 h45
  text ".PCB_File_Name_No_Path" at 10844.5,-384.25 h70
  text "Texas Instruments (TI) and/or its licensors do not warrant the accuracy or completeness of this specification" at 5825,-546.09 h45
  text "ENGINEER:" at 10794.5,-554.25 h45
  text "LAYOUT BY:" at 12299.5,-554.25 h45
  text "or any information contained therein. TI and/or its licensors do not warrant that this design will meet" at 5780.01,-658.75 h45
  text ".PRJ_Engineer" at 10844.5,-709.24 h70
  text ".PCB_Layout" at 12350,-709.24 h70
  text "the specifications, will be suitable for your application or fit for any particular purpose, or will operate in" at 5780.01,-771.42 h45
  text "ALTIUM DESIGNER VERSION:" at 12299.5,-864.25 h45
  text "an implementation. TI and/or its licensors do not warrant that the design is production worthy. You should" at 5780.01,-884.08 h45
  text "completely validate and test your design implementation to confirm the system functionality for your application." at 5825,-996.75 h45
  text ".print_Scale" at 10844.5,-997.58 h70
  text ".Application_BuildNumber" at 12350,-997.58 h70
  text "1" at 190.84,-1204.25 h70
  text "2" at 2686.5,-1204.25 h70
  text "3" at 5175.84,-1204.25 h70
  text "4" at 7682.51,-1204.25 h70
  text "5" at 10181.5,-1204.25 h70
  text "6" at 12686.5,-1204.25 h70
M10 Fab Notes:
  drawing of 191 lines, arcs and shapes, not listed
  text "DESIGN INFORMATION" at 11838.02,6745.25 h60
  text "(REFER ALSO ARRAY/PANEL PROFILING INFORMATION)" at 11476.46,6583.54 h60
  text "BOARD SIZE" at 10790.46,6579.25 h60
  text "X" at 11758.46,6451.43 h60
  text "100MM" at 11994,6444.25 h60
  text "120MM" at 11306.5,6440.76 h60
  text "Number of Layers :" at 11208.46,6344.25 h60
  text "4" at 12303.27,6334.25 h60
  text "MIN. TRACK WIDTH:" at 11208.46,6205.25 h60
  text "9" at 12302,6205.25 h60
  text "MIL" at 12459.46,6205.25 h60
  text "MIN. CLEARANCE:" at 11208.46,6073.25 h60
  text "7.7" at 12226.5,6072.76 h60
  text "MIL" at 12477,6046.65 h60
  text "MIN. VIA PAD SIZE:" at 11208.46,5941.25 h60
  text "19.69" at 12186,5935.25 h60
  text "MIL" at 12477,5918.65 h60
  text "0.15mm (5.91MIL)" at 11903.46,5799.54 h60
  text "EXTERNAL" at 12640,5799.65 h60
  text "MINIMUM ANNULAR RING" at 10879.23,5795.26 h60
  text "PER" at 11079.23,5677.26 h60
  text "IPC-D-275 CLASS 2 LEVEL C" at 11299.23,5677.25 h60
  text "MIL, HOLES" at 12787.46,5564.97 h60
  text "+/-" at 12395,5564.25 h60
  text "+/-" at 13249,5564.25 h60
  text "REGISTRATION TOLERANCES:" at 10879.23,5559.25 h60
  text "METAL" at 12079,5559.25 h60
  text "5" at 12655.2,5559.26 h60
  text "3" at 13488.2,5559.26 h60
  text "MIL" at 13604.46,5559.25 h60
  text "IMPEDENCE CONTROLLED BOARD:NO" at 10912,5410.25 h60
  text "MATERIAL:" at 10788.46,5186.79 h60
  text "FR-4 High Tg" at 11774.9,5046.46 h60
  text "FR-408" at 11209.46,5037.89 h60
  text "OTHER" at 12697.46,5037.89 h60
  text "X" at 11613,5036.25 h60
  text "THICKNESS:" at 10790,4881.25 h60
  text "63 MIL (1.6mm) +/-10%" at 11449,4876.25 h60
  text "OTHER" at 12814.46,4870.89 h60
  text "X" at 11314,4868.25 h60
  text "TOLERANCE:" at 10863.23,4712.89 h60
  text "X" at 11702.53,4712.89 h60
  text "ANSI IPC-6012 TYPE 3 CLASS 2" at 11889.48,4712.89 h60
  text "OTHER +/-" at 11889.46,4556.89 h60
  text "BOW & TWIST:" at 10863.23,4399.89 h60
  text "X" at 11702.53,4399.89 h60
  text "ANSI IPC-6012 TYPE 3 CLASS 2" at 11889.48,4399.89 h60
  text "OTHER +/-" at 11889.46,4241.38 h60
  text "DRILLING:" at 10788.46,4102.89 h60
  text "REFERENCE:" at 10863.23,3985.89 h60
  text "X" at 11511.46,3985.89 h60
  text "AS SHOWN" at 11698.46,3985.89 h60
  text "X" at 12412.46,3985.89 h60
  text "NC_DRILL FILES" at 12549.46,3985.89 h60
  text "PTH MIN COPPER THICKNESS:" at 10863.23,3827.89 h60
  text "X" at 12213.46,3827.89 h60
  text "1MIL" at 12350.46,3827.89 h60
  text "OTHER" at 12847.46,3827.89 h60
  text "BOARD FINISH:" at 10788.46,3668.89 h60
  text "SILKSCREEN:" at 10943.68,3550.89 h60
  text "X" at 11892.46,3550.89 h60
  text "TOP" at 12018.46,3550.89 h60
  text "BOTTOM" at 12529.46,3550.89 h60
  text "SILKSCREEN COLOR:" at 10943.68,3383.89 h60
  text "X" at 11891.42,3383.89 h60
  text "WHITE" at 12018.46,3383.89 h60
  text "OTHER" at 12529.46,3383.89 h60
  text "SOLDER RESIST COLOR:" at 10943.68,3213.89 h60
  text "X" at 11511.42,3054.69 h60
  text "GREEN" at 11638.46,3054.69 h60
  text "BLUE" at 12229.46,3054.69 h60
  text "OTHER" at 12767.46,3054.69 h60
  text "IMMERSION GOLD (ENIG)" at 11849.46,2866.18 h60
  text "ENEPIG" at 13187,2862.89 h60
  text "SURFACE FINISH:" at 10788.46,2861.89 h60
  text "X" at 11662.51,2861.89 h60
  text "IMM. TIN/SILVER OR EQUIV" at 11118,2704.89 h60
  text "OTHER" at 12549.46,2704.89 h60
  text "ARRAY/PANEL:" at 10788.46,2525.89 h60
  text "CUT AND TRIM PER MECH LAYER 1" at 11849.46,2521.61 h60
  text "N.C. ROUTE" at 11849.46,2369.89 h60
  text "X" at 12528.46,2369.89 h60
  text "V. SCORE" at 12715.46,2369.89 h60
  text "CERTIFICATION:" at 10788.46,2232.89 h60
  text "MATERIALS AND WORKMANSHIP FOR ALL PCBS" at 11513.46,2232.89 h60
  text "TO MEET OR EXCEED THE REQUIREMENTS OF:" at 11513.46,2134.89 h60
  text "X" at 11139.96,1998.39 h60
  text "ANSI IPC-A-600F CLASS ->" at 11278.96,1998.39 h60
  text "X" at 12918.02,1998.39 h60
  text "2" at 13036.96,1998.39 h60
  text "1" at 12721.96,1996.89 h60
  text "3" at 13390.96,1996.89 h60
  text "X" at 11142.02,1838.89 h60
  text "UL 94V-0" at 11278.96,1838.89 h60
  text "X" at 11954.02,1838.89 h60
  text "RoHS" at 12090.96,1838.89 h60
  text "OTHER" at 12735.36,1838.89 h60
  text "PER ORDER" at 13132.42,1838.89 h60
  text "ADDITIONAL REQUIREMENTS:" at 10788.46,1697.89 h60
  text "MICROSECTION:" at 10863.23,1582.89 h60
  text "YES" at 11768.96,1582.89 h60
  text "REQUIRED" at 12630.46,1426.75 h60
  text "BARE BOARD ELEC. TEST:" at 10863.23,1423.89 h60
  text "NONE" at 12168.96,1423.89 h60
  text "X" at 12503.46,1423.89 h60
  text "PER ORDER" at 13222.46,1423.89 h60
  text "MANUFACTURER'S UL:" at 10863.23,1266.89 h60
  text "RAIL" at 12028.96,1262.61 h60
  text "METAL" at 12520.77,1262.61 h60
  text "X" at 12896,1262.25 h60
  text "SILK" at 13032.46,1262.61 h60
  text "VIA`S TO BE TENTED:" at 10843,1075.25 h60
  text "Refer NOTE" at 11748,1075.25 h60
M11 Gerber Information:
  lines w10: -841,-870.91 5759,-870.91 ; -841,-667.58 5761,-667.58 ; -841,-464.25 -841,-1074.25 3164,-1074.25 5761,-1074.25 5761,-464.25 -840.5,-464.25 -840.5,-1074.25 735,-1074.25 ; 1624,-1074.25 1624,-464.25 ; 2891,-667.58 2891,-464.25 ; 3731,-667.58 3731,-464.25 ; 4353,-1080.75 4353,-877.91
  text "ALL ARTWORK VIEWED FROM TOP SIDE" at -777.5,-596.41 h60
  text "BOARD #:" at 1699,-596.41 h60
  text ".PRJ_Number" at 2244.5,-596.41 h60
  text "REV:" at 3089,-596.41 h60
  text ".PCB_Rev" at 3380.5,-596.41 h60
  text "SVN REV:" at 3927,-596.41 h60
  text ".VersionControl_RevNumber" at 4433,-596.41 h60
  text "LAYER NAME =" at -777.5,-799.24 h60
  text "TID #:" at 1699,-799.75 h60
  text ".TID" at 2244.5,-799.75 h60
  text "PLOT NAME =" at -777.5,-1005.08 h60
  text ".plot_File_Name" at 28,-1005.08 h60
  text "GENERATED    :" at 1701,-1005.08 h60
  text ".Print_Date" at 2570.5,-1005.08 h60
  text ".Print_Time" at 3299.5,-1005.08 h60
  text "TEXAS INSTRUMENTS" at 4564,-1005.08 h60
M12 Stackup:
  drawing of 295 lines, arcs and shapes, not listed
  text "Layer" at 6102.5,7634.75 h60
  text "Name" at 6512.41,7634.75 h60
  text "Material" at 7442.16,7634.75 h60
  text "Thickness" at 8301.92,7634.75 h60
  text "Constant" at 8951.76,7634.75 h60
  text "Board Layer Stack" at 9521.62,7634.75 h60
  text "1" at 6102.5,7514.75 h60
  text "Top Overlay" at 6512.41,7514.75 h60
  text "2" at 6102.5,7394.75 h60
  text "Top Solder" at 6512.41,7394.75 h60
  text "Solder Resist" at 7442.16,7394.75 h60
  text "0.40mil" at 8301.92,7394.75 h60
  text "3.5" at 8951.76,7394.75 h60
  text "3" at 6102.5,7274.75 h60
  text "Top Layer" at 6512.41,7274.75 h60
  text "Copper" at 7442.16,7274.75 h60
  text "2.80mil" at 8301.92,7274.75 h60
  text "4" at 6102.5,7154.75 h60
  text "Dielectric1" at 6512.41,7154.75 h60
  text "FR-4 High Tg" at 7442.16,7154.75 h60
  text "8.00mil" at 8301.92,7154.75 h60
  text "4.8" at 8951.76,7154.75 h60
  text "5" at 6102.5,7034.75 h60
  text "GND" at 6512.41,7034.75 h60
  text "Copper" at 7442.16,7034.75 h60
  text "2.80mil" at 8301.92,7034.75 h60
  text "6" at 6102.5,6914.75 h60
  text "Dielectric 2" at 6512.41,6914.75 h60
  text "FR-4 High Tg" at 7442.16,6914.75 h60
  text "35.00mil" at 8301.92,6914.75 h60
  text "4.2" at 8951.76,6914.75 h60
  text "7" at 6102.5,6794.75 h60
  text "PWR" at 6512.41,6794.75 h60
  text "Copper" at 7442.16,6794.75 h60
  text "2.80mil" at 8301.92,6794.75 h60
  text "8" at 6102.5,6674.75 h60
  text "Dielectric 3" at 6512.41,6674.75 h60
  text "FR-4 High Tg" at 7442.16,6674.75 h60
  text "8.00mil" at 8301.92,6674.75 h60
  text "4.2" at 8951.76,6674.75 h60
  text "9" at 6102.5,6554.75 h60
  text "Bottom Layer" at 6512.41,6554.75 h60
  text "Copper" at 7442.16,6554.75 h60
  text "2.80mil" at 8301.92,6554.75 h60
  text "10" at 6102.5,6434.75 h60
  text "Bottom Solder" at 6512.41,6434.75 h60
  text "Solder Resist" at 7442.16,6434.75 h60
  text "0.40mil" at 8301.92,6434.75 h60
  text "3.5" at 8951.76,6434.75 h60
  text "11" at 6102.5,6314.75 h60
  text "Bottom Overlay" at 6512.41,6314.75 h60
M13 Component Bodies Top:
  text ".Layer_Name" at 28,-799.24 h60
M14 Component Bodies Bottom:
  text ".Layer_Name" at 28,-799.24 h60
M15 Courtyards Top:
  text ".Layer_Name" at 28,-799.24 h60
M16 Courtyards Bottom:
  text ".Layer_Name" at 28,-799.24 h60
Drill Drawing:
  circle w1: c6549.25,2916.25 r15
  circle w1: c6549.25,2916.25 r25
  lines w1: 6524.25,1841.25 6524.25,1853.75 6536.75,1866.25 6524.25,1878.75 6524.25,1891.25 6536.75,1891.25 6549.25,1878.75 6561.75,1891.25 6574.25,1891.25 6574.25,1878.75 6561.75,1866.25 6574.25,1853.75 6574.25,1841.25 6561.75,1841.25 6549.25,1853.75 6536.75,1841.25 6524.25,1841.25 ; 6524.25,1991.25 6574.25,1991.25 6574.25,2041.25 6524.25,2041.25 6524.25,1991.25 ; 6524.25,2291.25 6549.25,2303.75 6574.25,2291.25 6561.75,2316.25 6574.25,2341.25 6549.25,2328.75 6524.25,2341.25 6536.75,2316.25 6524.25,2291.25 ; 6524.25,2591.25 6524.25,2603.75 6536.75,2616.25 6524.25,2628.75 6524.25,2641.25 6536.75,2641.25 6549.25,2628.75 6561.75,2641.25 6574.25,2641.25 6574.25,2628.75 6561.75,2616.25 6574.25,2603.75 6574.25,2591.25 6561.75,2591.25 6549.25,2603.75 6536.75,2591.25 6524.25,2591.25 ; 6524.25,2753.75 6536.75,2753.75 6549.25,2741.25 6561.75,2753.75 6574.25,2753.75 6561.75,2766.25 6574.25,2778.75 6561.75,2778.75 6549.25,2791.25 6536.75,2778.75 6524.25,2778.75 6536.75,2766.25 6524.25,2753.75 ; 6524.25,3053.75 6536.75,3053.75 6536.75,3041.25 6561.75,3041.25 6561.75,3053.75 6574.25,3053.75 6574.25,3078.75 6561.75,3078.75 6561.75,3091.25 6536.75,3091.25 6536.75,3078.75 6524.25,3078.75 6524.25,3053.75 ; 6534.25,2301.25 6549.25,2308.75 6564.25,2301.25 6556.75,2316.25 6564.25,2331.25 6549.25,2323.75 6534.25,2331.25 6541.75,2316.25 6534.25,2301.25 ; 6534.25,2601.25 6534.25,2608.75 6541.75,2616.25 6534.25,2623.75 6534.25,2631.25 6541.75,2631.25 6549.25,2623.75 6556.75,2631.25 6564.25,2631.25 6564.25,2623.75 6556.75,2616.25 6564.25,2608.75 6564.25,2601.25 6556.75,2601.25 6549.25,2608.75 6541.75,2601.25 6534.25,2601.25 ; 6534.25,2758.75 6541.75,2758.75 6549.25,2751.25 6556.75,2758.75 6564.25,2758.75 6556.75,2766.25 6564.25,2773.75 6556.75,2773.75 6549.25,2781.25 6541.75,2773.75 6534.25,2773.75 6541.75,2766.25 6534.25,2758.75 ; 6534.25,3058.75 6541.75,3058.75 6541.75,3051.25 6556.75,3051.25 6556.75,3058.75 6564.25,3058.75 6564.25,3073.75 6556.75,3073.75 6556.75,3081.25 6541.75,3081.25 6541.75,3073.75 6534.25,3073.75 6534.25,3058.75
  lines w15: 6456.12,1796.25 10335.1,1796.25 ; 6456.12,3146.25 10335.1,3146.25 ; 7007,1646.25 7007,3296.25 ; 7704.81,1646.25 7704.81,3296.25 ; 9050.42,1646.25 9050.42,3296.25 ; 9556.29,1646.25 9556.29,3296.25 ; 6456.12,1646.25 10335.1,1646.25 10335.1,3296.25 6456.12,3296.25 6456.12,1646.25
  text "Symbol" at 6546.12,3191.25 h72
  text "Hit Count" at 7052,3191.25 h72
  text "Finished Hole Size" at 7749.81,3191.25 h72
  text "Plated" at 9095.42,3191.25 h72
  text "Hole Type" at 9601.29,3191.25 h72
  text "2" at 7052,3041.25 h60
  text "51.18mil (1.300mm)" at 7749.81,3041.25 h60
  text "PTH" at 9095.42,3041.25 h60
  text "Round" at 9601.29,3041.25 h60
  text "4" at 7052,2891.25 h60
  text "35.43mil (0.900mm)" at 7749.81,2891.25 h60
  text "PTH" at 9095.42,2891.25 h60
  text "Round" at 9601.29,2891.25 h60
  text "4" at 7052,2741.25 h60
  text "40.00mil (1.016mm)" at 7749.81,2741.25 h60
  text "PTH" at 9095.42,2741.25 h60
  text "Round" at 9601.29,2741.25 h60
  text "4" at 7052,2591.25 h60
  text "59.06mil (1.500mm)" at 7749.81,2591.25 h60
  text "PTH" at 9095.42,2591.25 h60
  text "Round" at 9601.29,2591.25 h60
  text "C" at 6536.75,2453.75 h50
  text "4" at 7052,2441.25 h60
  text "125.98mil (3.200mm)" at 7749.81,2441.25 h60
  text "PTH" at 9095.42,2441.25 h60
  text "Round" at 9601.29,2441.25 h60
  text "6" at 7052,2291.25 h60
  text "47.24mil (1.200mm)" at 7749.81,2291.25 h60
  text "PTH" at 9095.42,2291.25 h60
  text "Round" at 9601.29,2291.25 h60
  text "A" at 6536.75,2153.75 h50
  text "16" at 7052,2141.25 h60
  text "66.93mil (1.700mm)" at 7749.81,2141.25 h60
  text "PTH" at 9095.42,2141.25 h60
  text "Round" at 9601.29,2141.25 h60
  text "39" at 7052,1991.25 h60
  text "7.87mil (0.200mm)" at 7749.81,1991.25 h60
  text "PTH" at 9095.42,1991.25 h60
  text "Round" at 9601.29,1991.25 h60
  text "424" at 7052,1841.25 h60
  text "15.00mil (0.381mm)" at 7749.81,1841.25 h60
  text "PTH" at 9095.42,1841.25 h60
  text "Round" at 9601.29,1841.25 h60
  text "503 Total" at 7052,1691.25 h60
  text "DRILL TABLE" at 6706,1357.25 h60
  text "FOR 7.874MIL DRILL +0/-7.874MIL" at 6706,1248.25 h60
  text "FOR 15MIL DRILL +0/-15MIL" at 6704,1150.25 h60
  text "FOR PTH DRILL +/-3MIL" at 6704,1042.25 h60
  text "NOTE:" at 6703,774.25 h60
  text "15MIL Vias are Tented in both the sides." at 6702,683.25 h60
  text "7.874MIL vias are not Tented." at 6704,585.25 h60
  text ".Layer_Name" at 28,-799.24 h60
M17 Embedded Cavity:
  text ".Layer_Name" at 28,-799.24 h60
M18 Embedded Assembly:
  text ".Layer_Name" at 28,-799.24 h60
M19 Embedded Keepout:
  text ".Layer_Name" at 28,-799.24 h60

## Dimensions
0,3937.01 to 4724.41,3937.01 on M2 Board Dimensions
0,0 to 0,3937.01 on M2 Board Dimensions
-549,-340.75 to 451,-340.75 on M2 Board Dimensions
